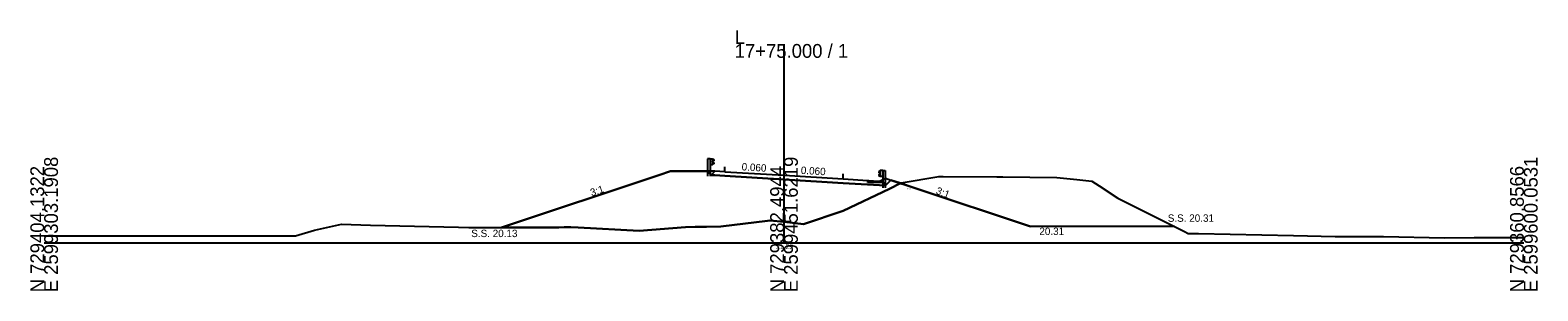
# Model space of a CAD drawing. Extents: x -26 to 3303, y -10 to 9555.
# Drawn here: x 997.2 to 1302.8, y 5490.3 to 5543.1 of the extents above; entities that cross this region are included whole.
import ezdxf

# ---------------------------------------------------------------- set-up
doc = ezdxf.new("R2010")
doc.units = 0
for name, color, linetype in [('Exist Cross Section Cell', 7, 'Continuous'), ('Exist XS Center Line Elevation Label', 7, 'Continuous'), ('Exist XS Ground Line', 7, 'Continuous'), ('Prop XS Ditch Slope Text', 7, 'Continuous'), ('Prop XS Ditch Standard Text', 7, 'Continuous'), ('Prop XS Dump Level', 7, 'Continuous'), ('Prop XS Earthwork Shape', 7, 'Continuous'), ('Prop XS EOT Tick Mark', 7, 'Continuous'), ('Prop XS Finish Grade', 7, 'Continuous'), ('Prop XS Finish Grade Earthwork', 7, 'Continuous'), ('Prop XS Finish Grade Paved Shoulder', 7, 'Continuous'), ('Prop XS Finish Grade Pavement', 7, 'Continuous'), ('Prop XS Pvmt Edge Slope', 7, 'Continuous'), ('Prop XS SE Text', 7, 'Continuous'), ('Prop XS Side Slope Text', 7, 'Continuous'), ('Prop XS SS Elevation Text', 7, 'Continuous'), ('Prop XS Subgrade Earthwork', 7, 'Continuous'), ('Typical Curb CELL', 7, 'Continuous'), ('Typical Guardrail CELL', 7, 'Continuous')]:
    doc.layers.add(name, color=color, linetype=linetype)

msp = doc.modelspace()

# ---------------------------------------------------------------- linework, layer by layer
at = {"layer": 'Exist Cross Section Cell'}
for p, q in [((1150, 5500), (1150, 5540.31)), ((1000, 5500), (1150, 5500)), ((1150, 5500), (1300, 5500))]:
    msp.add_line(p, q, dxfattribs=at)
at = {"layer": 'Exist XS Ground Line'}
msp.add_lwpolyline([(1000, 5501.47), (1000.6, 5501.47), (1010.01, 5501.47), (1017.86, 5501.47), (1028.44, 5501.47), (1050.94, 5501.47), (1054.82, 5502.59), (1060.25, 5503.81), (1066.15, 5503.59), (1084.01, 5503.19), (1086.1, 5503.12), (1104.34, 5503.15), (1105.45, 5503.18), (1106.81, 5503.18), (1108.28, 5503.16), (1120.61, 5502.48), (1130.05, 5503.22), (1131.99, 5503.26), (1134.26, 5503.27), (1137.22, 5503.37), (1146.65, 5504.48), (1147.12, 5504.55), (1150, 5504.25), (1153.93, 5503.84), (1162, 5506.48), (1171.39, 5510.98), (1173.78, 5512.16), (1181.38, 5513.44), (1182.29, 5513.44), (1193.14, 5513.41), (1194.4, 5513.39), (1205.29, 5513.25), (1209.34, 5512.83), (1212.38, 5512.49), (1213.88, 5511.58), (1217.65, 5509.11), (1226.63, 5504.59), (1231.2, 5502.3), (1231.91, 5501.89), (1234.05, 5501.9), (1253.27, 5501.51), (1261.72, 5501.34), (1264.9, 5501.32), (1271.54, 5501.3), (1283.93, 5501.03), (1289.93, 5501.08), (1300, 5501.1)], dxfattribs=at)
at = {"layer": 'Prop XS Dump Level'}
for p, q in [((1138, 5514.43), (1150, 5513.71)), ((1150, 5513.71), (1162, 5512.99))]:
    msp.add_line(p, q, dxfattribs=at)
at = {"layer": 'Prop XS Earthwork Shape'}
for points in [[(1104.34, 5503.15), (1105.45, 5503.18), (1106.81, 5503.18), (1108.28, 5503.16), (1120.61, 5502.48), (1130.05, 5503.22), (1131.99, 5503.26), (1134.26, 5503.27), (1137.22, 5503.37), (1146.65, 5504.48), (1147.12, 5504.55), (1150, 5504.25), (1153.93, 5503.84), (1162, 5506.48), (1171.39, 5510.98), (1173.65, 5512.09), (1171.68, 5512.75), (1170.56, 5511.64), (1162, 5512.15), (1150, 5512.87), (1138, 5513.59), (1136, 5513.71), (1135.21, 5513.76), (1134.43, 5514.55), (1127, 5514.55), (1124.64, 5513.76), (1092.75, 5503.13)], [(1171.68, 5512.75), (1173.65, 5512.09), (1171.39, 5510.98), (1162, 5506.48), (1153.93, 5503.84), (1150, 5504.25), (1147.12, 5504.55), (1146.65, 5504.48), (1137.22, 5503.37), (1134.26, 5503.27), (1131.99, 5503.26), (1130.05, 5503.22), (1120.61, 5502.48), (1108.28, 5503.16), (1106.81, 5503.18), (1105.45, 5503.18), (1104.34, 5503.15), (1092.75, 5503.13), (1124.64, 5513.76), (1127, 5514.55), (1134.43, 5514.55), (1135.21, 5513.76), (1136, 5513.71), (1138, 5513.59), (1150, 5512.87), (1162, 5512.15), (1170.56, 5511.64)], [(1194.4, 5513.39), (1205.29, 5513.25), (1209.34, 5512.83), (1212.38, 5512.49), (1213.88, 5511.58), (1217.65, 5509.11), (1226.63, 5504.59), (1229.18, 5503.31), (1200.01, 5503.31), (1176.4, 5511.18), (1173.65, 5512.09), (1173.78, 5512.16), (1181.38, 5513.44), (1182.29, 5513.44), (1193.14, 5513.41)], [(1173.78, 5512.16), (1181.38, 5513.44), (1182.29, 5513.44), (1193.14, 5513.41), (1194.4, 5513.39), (1205.29, 5513.25), (1209.34, 5512.83), (1212.38, 5512.49), (1213.88, 5511.58), (1217.65, 5509.11), (1226.63, 5504.59), (1229.18, 5503.31), (1200.01, 5503.31), (1176.4, 5511.18), (1173.65, 5512.09)]]:
    msp.add_lwpolyline(points, close=True, dxfattribs=at)
at = {"layer": 'Prop XS EOT Tick Mark'}
for p, q in [((1138, 5514.43), (1138, 5515.43)), ((1162, 5512.99), (1162, 5513.99))]:
    msp.add_line(p, q, dxfattribs=at)
at = {"layer": 'Prop XS Finish Grade'}
for p, q in [((1136, 5514.55), (1134.43, 5514.55)), ((1170.03, 5512.87), (1170.56, 5513.12)), ((1170.56, 5513.12), (1171.68, 5512.75))]:
    msp.add_line(p, q, dxfattribs=at)
at = {"layer": 'Prop XS Finish Grade Earthwork'}
for p, q in [((1127, 5514.55), (1124.64, 5513.76)), ((1134.43, 5514.55), (1127, 5514.55)), ((1124.64, 5513.76), (1092.75, 5503.13)), ((1171.68, 5512.75), (1176.4, 5511.18)), ((1176.4, 5511.18), (1200.01, 5503.31)), ((1229.18, 5503.31), (1200.01, 5503.31))]:
    msp.add_line(p, q, dxfattribs=at)
at = {"layer": 'Prop XS Finish Grade Paved Shoulder'}
for p, q in [((1138, 5514.43), (1136, 5514.55)), ((1162, 5512.99), (1167, 5512.69))]:
    msp.add_line(p, q, dxfattribs=at)
at = {"layer": 'Prop XS Finish Grade Pavement'}
for p, q in [((1138, 5514.43), (1150, 5513.71)), ((1150, 5513.71), (1162, 5512.99))]:
    msp.add_line(p, q, dxfattribs=at)
at = {"layer": 'Prop XS Pvmt Edge Slope'}
for p, q in [((1135.21, 5513.76), (1134.43, 5514.55)), ((1136, 5514.55), (1135.21, 5513.76)), ((1170.01, 5512.19), (1170.56, 5511.64)), ((1170.56, 5511.64), (1171.68, 5512.75))]:
    msp.add_line(p, q, dxfattribs=at)
at = {"layer": 'Prop XS Subgrade Earthwork'}
for p, q in [((1135.21, 5513.76), (1134.43, 5514.55)), ((1136, 5513.71), (1135.21, 5513.76)), ((1138, 5513.59), (1136, 5513.71)), ((1150, 5512.87), (1138, 5513.59)), ((1162, 5512.15), (1150, 5512.87)), ((1162, 5512.15), (1170.56, 5511.64)), ((1170.56, 5511.64), (1171.68, 5512.75))]:
    msp.add_line(p, q, dxfattribs=at)
at = {"layer": 'Typical Curb CELL'}
for p, q in [((1166.99, 5512.27), (1167, 5512.68)), ((1170.01, 5512.19), (1166.99, 5512.27)), ((1167, 5512.69), (1167, 5512.69)), ((1167.01, 5512.69), (1169.33, 5512.55)), ((1167.23, 5512.42), (1167.32, 5512.53)), ((1167.35, 5512.42), (1167.23, 5512.42)), ((1167.32, 5512.53), (1167.35, 5512.42)), ((1167.99, 5512.35), (1168.06, 5512.46)), ((1168.16, 5512.38), (1167.99, 5512.35)), ((1168.06, 5512.46), (1168.16, 5512.38)), ((1168.48, 5512.38), (1168.57, 5512.5)), ((1168.6, 5512.39), (1168.48, 5512.38)), ((1168.57, 5512.5), (1168.6, 5512.39)), ((1169.24, 5512.31), (1169.31, 5512.43)), ((1169.41, 5512.35), (1169.24, 5512.31)), ((1169.31, 5512.43), (1169.41, 5512.35)), ((1169.33, 5512.55), (1170.03, 5512.87)), ((1169.83, 5512.54), (1169.84, 5512.45)), ((1169.98, 5512.49), (1169.83, 5512.54)), ((1169.84, 5512.45), (1169.98, 5512.49)), ((1170.01, 5512.19), (1170.03, 5512.87))]:
    msp.add_line(p, q, dxfattribs=at)
for centre in [(1167.09, 5512.51), (1167.13, 5512.63), (1167.49, 5512.55), (1167.55, 5512.37), (1167.6, 5512.33), (1167.64, 5512.46), (1167.71, 5512.45), (1167.76, 5512.48), (1167.81, 5512.37), (1168, 5512.4), (1168.21, 5512.38), (1168.23, 5512.43), (1168.24, 5512.49), (1168.29, 5512.34), (1168.39, 5512.39), (1168.48, 5512.39), (1168.6, 5512.34), (1168.8, 5512.34), (1168.85, 5512.3), (1168.89, 5512.43), (1169.01, 5512.45), (1169.06, 5512.34), (1169.25, 5512.37), (1169.28, 5512.27), (1169.46, 5512.35), (1169.48, 5512.4), (1169.73, 5512.36), (1169.85, 5512.31), (1169.95, 5512.58)]:
    msp.add_circle(centre, 0.00802, dxfattribs=at)
msp.add_arc((1167.01, 5512.68), 0.0104, 86.5213, 178.5693, dxfattribs=at)
at = {"layer": 'Typical Guardrail CELL'}
for p, q in [((1135, 5517.03), (1134.5, 5517.03)), ((1134.5, 5517.03), (1134.5, 5514.55)), ((1135, 5514.55), (1134.5, 5514.55)), ((1134.5, 5514.55), (1134.5, 5513.54)), ((1135, 5517.03), (1135, 5514.55)), ((1135, 5517.03), (1135.5, 5517.03)), ((1135, 5515.87), (1135.5, 5515.87)), ((1135, 5514.55), (1135, 5513.54)), ((1135.5, 5517.03), (1135.5, 5515.87)), ((1135.5, 5517.03), (1135.79, 5516.83)), ((1135.5, 5516.5), (1135.79, 5516.7)), ((1135.5, 5516.45), (1135.5, 5516.5)), ((1135.5, 5516.45), (1135.5, 5516.41)), ((1135.5, 5516.41), (1135.79, 5516.2)), ((1135.5, 5515.87), (1135.79, 5516.08)), ((1169.53, 5514.65), (1169.24, 5514.45)), ((1170.03, 5514.65), (1169.53, 5514.65)), ((1169.53, 5514.65), (1169.53, 5513.49)), ((1170.03, 5514.65), (1170.03, 5512.17)), ((1170.03, 5514.65), (1170.53, 5514.65)), ((1170.53, 5514.65), (1170.53, 5512.17)), ((1169.53, 5514.12), (1169.24, 5514.32)), ((1169.53, 5514.03), (1169.24, 5513.82)), ((1169.53, 5513.49), (1169.24, 5513.7)), ((1169.53, 5514.07), (1169.53, 5514.12)), ((1169.53, 5514.07), (1169.53, 5514.03)), ((1170.03, 5513.49), (1169.53, 5513.49)), ((1170.03, 5512.17), (1170.53, 5512.17)), ((1170.03, 5512.17), (1170.03, 5511.16)), ((1170.53, 5512.17), (1170.53, 5511.16))]:
    msp.add_line(p, q, dxfattribs=at)
for centre, start, end in [((1135.74, 5516.77), 304.9888, 54.997), ((1135.74, 5516.14), 304.9634, 54.9941), ((1169.29, 5514.39), 125.003, 235.0112), ((1169.29, 5513.76), 125.0059, 235.0366)]:
    msp.add_arc(centre, 0.0776, start, end, dxfattribs=at)

# ---------------------------------------------------------------- texts
at = {"layer": 'Exist Cross Section Cell'}
for s, p in [('L', (1140, 5540.31)), ('17+75.000 / 1', (1140, 5537.51))]:
    msp.add_text(s, height=2.8, dxfattribs=at).set_placement(p)
for s, p in [('N 729404.1322', (1000, 5490)), ('E 2599303.1908', (1002.8, 5490)), ('N 729382.4944', (1150, 5490)), ('E 2599451.6219', (1152.8, 5490)), ('N 729360.8566', (1300, 5490)), ('E 2599600.0531', (1302.8, 5490))]:
    msp.add_text(s, height=2.8, rotation=90, dxfattribs=at).set_placement(p)
at = {"layer": 'Exist XS Center Line Elevation Label'}
msp.add_text('21.25', height=1, dxfattribs=at).set_placement((1148.39, 5498.75))
at = {"layer": 'Prop XS Ditch Slope Text'}
msp.add_text('3:1', height=1.5, rotation=338.8386, dxfattribs=at).set_placement((1180.66, 5510.01))
at = {"layer": 'Prop XS Ditch Standard Text'}
msp.add_text('20.31', height=1.5, dxfattribs=at).set_placement((1201.77, 5501.62))
at = {"layer": 'Prop XS Dump Level'}
for s, height, p in [('Case1', 0.04, (1130, 5514.51)), ('Case1', 0.04, (1170, 5512.35)), ('Eop', 0.3, (1175, 5510.86))]:
    msp.add_text(s, height=height, dxfattribs=at).set_placement(p)
at = {"layer": 'Prop XS SE Text'}
for p in [(1141.38, 5514.72), (1153.38, 5514)]:
    msp.add_text('0.060', height=1.5, rotation=356.5664, dxfattribs=at).set_placement(p)
at = {"layer": 'Prop XS Side Slope Text'}
msp.add_text('3:1', height=1.5, rotation=18.4349, dxfattribs=at).set_placement((1111, 5509.44))
at = {"layer": 'Prop XS SS Elevation Text'}
for s, p in [('S.S. 20.31', (1227.81, 5504.29)), ('S.S. 20.13', (1086.59, 5501.19))]:
    msp.add_text(s, height=1.5, dxfattribs=at).set_placement(p)

doc.saveas('drawing.dxf')
